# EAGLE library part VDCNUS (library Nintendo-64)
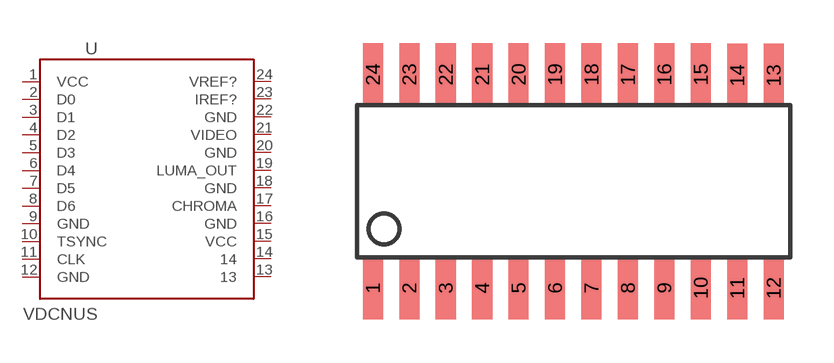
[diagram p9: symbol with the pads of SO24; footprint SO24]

Designator prefix -

## VDCNUS  [SO24]
1  VCC  pwr
2  D0  in
3  D1  in
4  D2  in
5  D3  in
6  D4  in
7  D5  in
8  D6  in
9  GND  pwr
10  TSYNC  in
11  CLK  in
12  GND  pwr
13  13
14  14
15  VCC  pwr
16  GND  pwr
17  CHROMA  out
18  GND  pwr
19  LUMA_OUT  out
20  GND  pwr
21  VIDEO  out
22  GND  pwr
23  IREF?
24  VREF?

## Footprint SO24 (pad centres in mm)
smd 0.7 x 2.2: 1 -7.62,-3.707; 2 -6.35,-3.707; 3 -5.08,-3.707; 4 -3.81,-3.707; 5 -2.54,-3.707; 6 -1.27,-3.707; 7 0,-3.707; 8 1.27,-3.707; 9 2.54,-3.707; 10 3.81,-3.707; 11 5.08,-3.707; 12 6.35,-3.707; 13 6.35,3.707; 14 5.08,3.707; 15 3.81,3.739; 16 2.54,3.739; 17 1.27,3.739; 18 0,3.739; 19 -1.27,3.739; 20 -2.54,3.739; 21 -3.81,3.739; 22 -5.08,3.739; 23 -6.35,3.739; 24 -7.62,3.739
